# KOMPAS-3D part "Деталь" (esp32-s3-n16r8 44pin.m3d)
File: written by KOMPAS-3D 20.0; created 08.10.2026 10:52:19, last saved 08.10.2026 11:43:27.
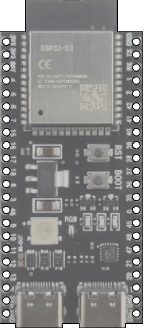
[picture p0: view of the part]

Document properties: Полное имя файла: D:\myProjects\Progect_esp32\box_compas\esp32\esp32-s3-n16r8 44pin.m3d

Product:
- Part/product: Деталь
    Масса: 0.019451

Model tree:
1. Эскиз:1
2. Элемент выдавливания:1
     Расстояние 1 = 1.5
3. Эскиз:2  (with: Элемент выдавливания:1)
4. Элемент выдавливания:3
     Расстояние 2 = 1.5
5. Эскиз:3  (with: Элемент выдавливания:1)
6. Элемент выдавливания:4
     Расстояние 2 = 1.5
7. Массив по сетке:1  (with: Элемент выдавливания:4, Эскиз:3)  (44 pattern instances)
     Шаг 1 = 25.4; Угол раствора = -90; Шаг 2 = 2.54

Referenced files in D:\RicWork\Project-EPS32\box_compas\: esp32-s3-n16r8.png
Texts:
  esp32-s3-n16r8.png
